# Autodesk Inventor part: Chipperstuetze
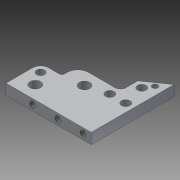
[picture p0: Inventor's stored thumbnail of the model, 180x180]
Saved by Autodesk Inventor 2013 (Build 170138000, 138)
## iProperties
Created: 2012-07
Part Number: Chipperstuetze
Material: Aluminium 6061
Document SubType Name: Modeling
Designer: rYan
Density: 2.71 g/cm^3
Mass: 6.7213 g
Surface Area: 21.3646 cm^2
Volume: 2.48019 cm^3
Author: rYan
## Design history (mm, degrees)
sketch "Skizze1"
  geometry: L1 (0, 0)-(26, 0); L2 (22, 19)-(12, 19); L3 (0, 37.322)-(0, -6.22) reference; L4 (-7.146, 0)-(38.524, 0) reference; L5 (0, 10)-(0, 0); L6 (0, 0)-(0, 0); L7 (24, 21)-(24, 25.5); L8 (24, 25.5)-(32, 31.102); L9 (32, 31.102)-(32, 0); L10 (32, 0)-(26, 0); L11 (8, 15)-(8, 14); L12 (3, 13)-(7, 13); A1 r 4 centre (12, 15) between (12, 19) and (8, 15); A2 r 3 centre (3, 10) between (3, 13) and (0, 10); A3 r 2 centre (22, 21) between (22, 19) and (24, 21); A4 r 1 centre (7, 14) between (7, 13) and (8, 14)
  constraints: 20 end point, 8 point on circle, 8 tangent, 4 centre point, 4 collinear, 3 parallel, 2 perpendicular, 2 point on line, 1 horizontal, 1 vertical
  dimensions: "d26" = 4 radius of A1; "d29" = 8 distance between parallel lines of L9 L7; "d30" = 125 deg angle of L8 L7; "d35" = 32 distance between parallel lines of L9 L3; "d36" = 25.5 distance from line of L4 L7.end; "d71" = 16 distance between parallel lines of L7 L11; "d72" = 3 radius of A2; "d74" = 2 radius of A3; "d98" = 1 radius of A4; "d102" = 6.5 distance from line of L7.end L2; "d103" = 15.5 vertical distance of L7.end A2.centre
extrude "Extrusion1" new body sketch "Skizze1" distance "d3" = 4; taper "d4" = 0 deg
sketch "Skizze2"
  geometry: L1 (0, 0)-(32, 0) reference; L2 (0, 37.322)-(0, -6.22) reference; L3 (22, 19)-(12, 19) reference; 2 further points
  dimensions: "d38" = 15.5 distance from line of point (15.5, 14) L2; "d104" = 5 distance from line of L3 point (15.5, 14)
hole "Chipachse" sketch "Skizze2" at (15.5, 14) diameter "d6" = 4; stored, may be unused: countersink angle "d10" = 90 deg, drill point angle "d12" = 118 deg; dims "d7" = 6, "d8" = 4, "d9" = 2, "d11" = 8
sketch "Skizze3"
  geometry: L1 (0, 0)-(32, 0) reference; L2 (0, 10)-(0, 0) reference; L3 (7, 13)-(3, 13) reference; 3 further points
  dimensions: "d17" = 6 distance from line of point (6, 5) L2; "d100" = 8 distance from line of point (6, 5) L3
hole "Aufbauachse" sketch "Skizze3" at (6, 5) diameter "d18" = 4; stored, may be unused: countersink angle "d22" = 90 deg, drill point angle "d24" = 118 deg; dims "d19" = 6, "d20" = 4, "d21" = 2, "d23" = 8
sketch "Skizze4"
  geometry: L1 (17.91, 0)-(0, 0) reference; L2 (0, 10)-(0, 0) reference; L3 (29, 16)-(23, 16); L4 (32, 0)-(32, 31.102) reference; L5 (22, 19)-(12, 19) reference
  constraints: 6 end point, 1 horizontal, 1 perpendicular, 1 vertical, 3 other
  dimensions: "d41" = 6 distance of L3.start L3.end; "d49" = 3 distance from line of L4 L3.start; "d50" = 3 distance between parallel lines of L3 L5
hole "Führungsmontage" sketch "Skizze4" at (23, 16), (29, 16) diameter "d42" = 3.2; stored, may be unused: countersink angle "d46" = 90 deg, drill point angle "d48" = 118 deg; dims "d43" = 6, "d44" = 4, "d45" = 2, "d47" = 8
sketch "Skizze5"
  geometry: L1 (-24, 25.5)-(-22, 19) reference; 2 further points
  dimensions: "d51" = 3 distance from line of point (-27, 24) L1; "d52" = 1.5 vertical distance of point (-27, 24) L1.start
hole "Fängerschraube" sketch "Skizze5" at (-27, 24) diameter "d53" = 3.2; stored, may be unused: countersink angle "d57" = 90 deg, drill point angle "d59" = 118 deg; dims "d54" = 6, "d55" = 4, "d56" = 2, "d58" = 8
sketch "Skizze6"
  geometry: L1 (-24, 25.5)-(-22, 19) reference; 2 further points
  dimensions: "d60" = 1.5 vertical distance of point (-29, 27) L1.start; "d61" = 5 distance from line of point (-29, 27) L1
hole "Fängerstift" sketch "Skizze6" at (-29, 27) diameter "d62" = 2.1; stored, may be unused: countersink angle "d66" = 90 deg, drill point angle "d68" = 118 deg; dims "d63" = 6, "d64" = 4, "d65" = 2, "d67" = 8
sketch "Skizze7"
  geometry: L1 (0, 0)-(32, 0) reference; L2 (32, 0)-(32, 4) reference; L3 (0, 4)-(32, 4) reference; L4 (0, 0)-(0, 4) reference; L5 (32, 2)-(0, 2); L6 (19.5, 4)-(19.5, 0); 4 further points
  constraints: 4 end point, 4 midpoint, 4 point on line, 1 perpendicular, 1 symmetric about line
  dimensions: "d75" = 19 distance of point (29, 2) point (10, 2); "d88" = 3 distance from line of L2 point (29, 2)
hole "Montage" sketch "Skizze7" at (19.5, 2), (10, 2), (29, 2) diameter "d77" = 2.459; stored, may be unused: countersink angle "d81" = 90 deg, drill point angle "d83" = 118 deg; dims "d78" = 4.5, "d79" = 4, "d80" = 2, "d82" = 6
sketch "Skizze8"
  geometry: L1 (0, 37.322)-(0, -6.22) reference; L2 (-6.4, 0)-(38.4, 0) reference; L3 (7, 13)-(3, 13) reference; 2 further points
  dimensions: "d89" = 3 distance from line of point (3, 10) L1; "d101" = 3 distance from line of L3 point (3, 10)
hole "Chip-Block" sketch "Skizze8" at (3, 10) diameter "d91" = 3; stored, may be unused: countersink angle "d95" = 90 deg, drill point angle "d97" = 118 deg; dims "d92" = 6, "d93" = 4, "d94" = 2, "d96" = 8
node "Volumenkörper1"
node "Projizierte Kontur1"
other parameters: "d32" = 16
